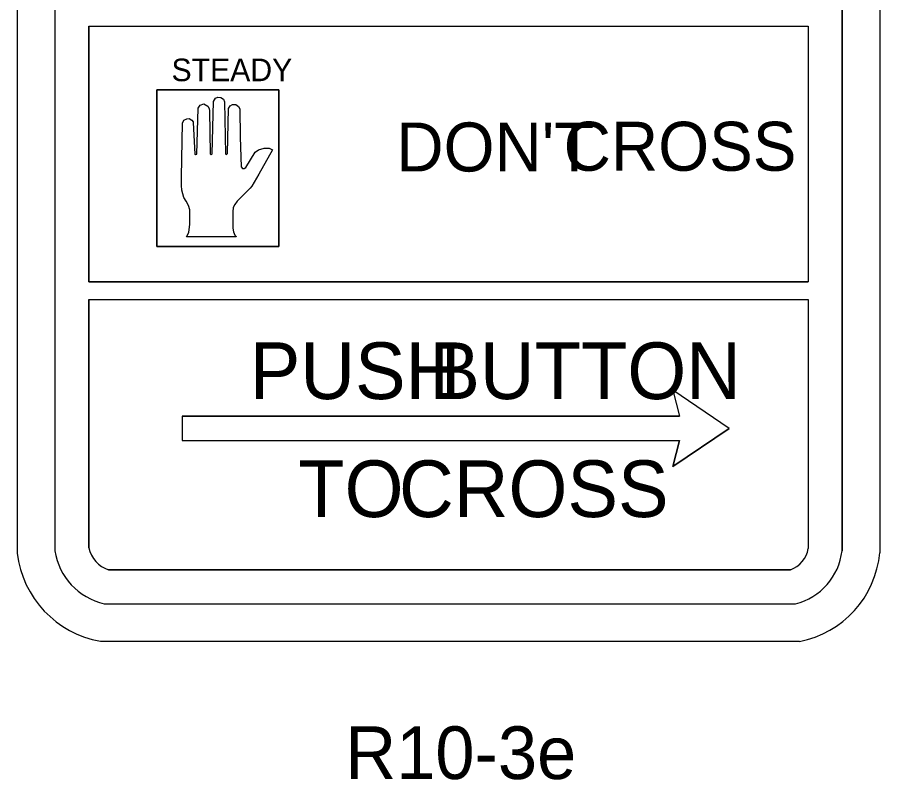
# Model space of a CAD drawing. Extents: x 1896459 to 1901611, y 1616229 to 1617416.
# Drawn here: x 1897736.4 to 1897851.1, y 1616868.6 to 1616970 of the extents above; entities that cross this region are included whole.
import ezdxf

# ---------------------------------------------------------------- set-up
doc = ezdxf.new("R2010")
doc.units = 0
for name, color, linetype in [('Level 8', 7, 'Continuous'), ('ROW_PR_Notes', 7, 'Continuous'), ('Signals_EX_Above Ground', 7, 'Continuous')]:
    doc.layers.add(name, color=color, linetype=linetype)

msp = doc.modelspace()

# ---------------------------------------------------------------- linework, layer by layer
at = {"layer": 'ROW_PR_Notes'}
for p, q in [((1897736.4, 1617066.24), (1897736.4, 1616898.74)), ((1897741.4, 1617066.11), (1897741.4, 1616899.07)), ((1897741.4, 1617066.11), (1897741.4, 1616899.07)), ((1897846.07, 1617066.11), (1897846.07, 1616899.07)), ((1897846.07, 1616899.07), (1897846.07, 1617066.11)), ((1897851.07, 1617066.41), (1897851.07, 1616898.82)), ((1897745.9, 1616968.81), (1897841.57, 1616968.81)), ((1897745.9, 1616968.81), (1897745.9, 1616934.8)), ((1897745.9, 1616934.8), (1897745.9, 1616968.81)), ((1897745.9, 1616968.81), (1897841.57, 1616968.81)), ((1897841.57, 1616968.81), (1897841.57, 1616934.8)), ((1897841.57, 1616968.81), (1897841.57, 1616934.8)), ((1897765.51, 1616940.81), (1897765.52, 1616940.82)), ((1897765.52, 1616940.82), (1897765.51, 1616940.81)), ((1897745.9, 1616934.8), (1897841.57, 1616934.8)), ((1897841.57, 1616934.8), (1897745.9, 1616934.8)), ((1897745.9, 1616932.47), (1897841.57, 1616932.47)), ((1897745.9, 1616932.47), (1897745.9, 1616899.47)), ((1897745.9, 1616899.47), (1897745.9, 1616932.47)), ((1897745.9, 1616932.47), (1897841.57, 1616932.47)), ((1897841.57, 1616932.47), (1897841.57, 1616899.38)), ((1897841.57, 1616932.47), (1897841.57, 1616899.38)), ((1897831.04, 1616915.34), (1897823.56, 1616920.42)), ((1897823.56, 1616920.42), (1897824.44, 1616916.98)), ((1897831.04, 1616915.34), (1897823.56, 1616920.42)), ((1897823.56, 1616920.42), (1897824.44, 1616916.98)), ((1897758.31, 1616916.98), (1897758.31, 1616913.71)), ((1897758.31, 1616916.98), (1897824.44, 1616916.98)), ((1897824.44, 1616916.98), (1897758.31, 1616916.98)), ((1897758.31, 1616916.98), (1897758.31, 1616913.71)), ((1897831.04, 1616915.34), (1897823.56, 1616910.27)), ((1897823.56, 1616910.27), (1897831.04, 1616915.34)), ((1897758.31, 1616913.71), (1897824.44, 1616913.71)), ((1897758.31, 1616913.71), (1897824.44, 1616913.71)), ((1897823.56, 1616910.27), (1897824.44, 1616913.71)), ((1897824.44, 1616913.71), (1897823.56, 1616910.27)), ((1897748.55, 1616896.54), (1897839.22, 1616896.54)), ((1897839.22, 1616896.54), (1897748.55, 1616896.54)), ((1897747.95, 1616892.04), (1897839.86, 1616892.04)), ((1897747.95, 1616892.04), (1897839.86, 1616892.04)), ((1897747.47, 1616887.04), (1897840.39, 1616887.04))]:
    msp.add_line(p, q, dxfattribs=at)
msp.add_lwpolyline([(1897754.95, 1616960.33), (1897771.2, 1616960.33), (1897771.2, 1616939.49), (1897754.95, 1616939.49)], close=True, dxfattribs=at)
for points in [[(1897754.95, 1616939.49), (1897771.2, 1616939.49), (1897771.2, 1616960.33), (1897754.95, 1616960.33), (1897754.95, 1616939.49)], [(1897765.51, 1616940.81), (1897758.89, 1616940.81), (1897759.23, 1616941.38), (1897759.35, 1616942.49), (1897759.36, 1616943.61), (1897759.34, 1616944.37), (1897759.18, 1616944.97), (1897758.86, 1616945.55), (1897758.55, 1616946.04), (1897758.28, 1616947.01), (1897758.22, 1616947.63), (1897758.23, 1616948.75), (1897758.39, 1616955.88), (1897758.55, 1616956.28), (1897758.93, 1616956.48), (1897759.28, 1616956.5), (1897759.62, 1616956.31), (1897759.79, 1616956.1), (1897759.81, 1616955.99), (1897760.02, 1616951.8), (1897760.09, 1616951.7), (1897760.15, 1616951.73), (1897760.27, 1616951.78), (1897760.45, 1616957.9), (1897760.71, 1616958.3), (1897761.22, 1616958.45), (1897761.74, 1616958.18), (1897761.92, 1616957.84), (1897761.94, 1616957.56), (1897762.07, 1616951.84), (1897762.18, 1616951.72), (1897762.32, 1616951.82), (1897762.48, 1616958.79), (1897762.78, 1616959.24), (1897763.08, 1616959.37), (1897763.47, 1616959.33), (1897763.82, 1616959.07), (1897763.96, 1616958.75), (1897764.1, 1616951.82), (1897764.23, 1616951.73), (1897764.35, 1616951.85), (1897764.49, 1616957.86), (1897764.71, 1616958.22), (1897765.01, 1616958.38), (1897765.48, 1616958.4), (1897765.83, 1616958.13), (1897765.98, 1616957.81), (1897766.06, 1616954.05), (1897766.17, 1616950.09), (1897766.34, 1616949.88), (1897766.59, 1616949.86), (1897766.78, 1616950.01), (1897768.04, 1616952.04), (1897768.47, 1616952.36), (1897769.23, 1616952.58), (1897769.89, 1616952.56), (1897770.34, 1616952.36), (1897768.51, 1616949.11), (1897767.61, 1616947.53), (1897767.36, 1616947.25), (1897767.05, 1616946.94), (1897766.57, 1616946.47), (1897766.06, 1616945.92), (1897765.63, 1616945.52), (1897765.31, 1616945.11), (1897765.12, 1616944.68), (1897765.07, 1616944.13), (1897765.08, 1616941.94), (1897765.16, 1616941.45), (1897765.35, 1616941.03), (1897765.52, 1616940.82)]]:
    msp.add_lwpolyline(points, dxfattribs=at)
for centre, radius, start, end in [((1897749.81, 1616900.34), 13.5, 186.8164, 260.0038), ((1897749.81, 1616900.34), 8.5, 188.5933, 257.393), ((1897749.81, 1616900.34), 8.5, 188.5933, 257.393), ((1897749.81, 1616900.34), 4, 192.5385, 251.5824), ((1897749.81, 1616900.34), 4, 192.5385, 251.5824), ((1897837.92, 1616900), 3.69, 290.4443, 350.2331), ((1897837.92, 1616900), 3.69, 290.4443, 350.2331), ((1897837.92, 1616900), 8.19, 283.6872, 353.4463), ((1897837.92, 1616900), 8.19, 283.6872, 353.4463), ((1897837.92, 1616900), 13.2, 280.7764, 354.8365)]:
    msp.add_arc(centre, radius, start, end, dxfattribs=at)
at = {"layer": 'Signals_EX_Above Ground'}
msp.add_lwpolyline([(1897765.51, 1616940.81), (1897758.89, 1616940.81), (1897759.23, 1616941.38), (1897759.35, 1616942.49), (1897759.36, 1616943.61), (1897759.34, 1616944.37), (1897759.18, 1616944.97), (1897758.86, 1616945.55), (1897758.55, 1616946.04), (1897758.28, 1616947.01), (1897758.22, 1616947.63), (1897758.23, 1616948.75), (1897758.39, 1616955.88), (1897758.55, 1616956.28), (1897758.93, 1616956.48), (1897759.28, 1616956.5), (1897759.62, 1616956.31), (1897759.79, 1616956.1), (1897759.81, 1616955.99), (1897760.02, 1616951.8), (1897760.09, 1616951.7), (1897760.15, 1616951.73), (1897760.27, 1616951.78), (1897760.45, 1616957.9), (1897760.71, 1616958.3), (1897761.22, 1616958.45), (1897761.74, 1616958.18), (1897761.92, 1616957.84), (1897761.94, 1616957.56), (1897762.07, 1616951.84), (1897762.18, 1616951.72), (1897762.32, 1616951.82), (1897762.48, 1616958.79), (1897762.78, 1616959.24), (1897763.08, 1616959.37), (1897763.47, 1616959.33), (1897763.82, 1616959.07), (1897763.96, 1616958.75), (1897764.1, 1616951.82), (1897764.23, 1616951.73), (1897764.35, 1616951.85), (1897764.49, 1616957.86), (1897764.71, 1616958.22), (1897765.01, 1616958.38), (1897765.48, 1616958.4), (1897765.83, 1616958.13), (1897765.98, 1616957.81), (1897766.06, 1616954.05), (1897766.17, 1616950.09), (1897766.34, 1616949.88), (1897766.59, 1616949.86), (1897766.78, 1616950.01), (1897768.04, 1616952.04), (1897768.47, 1616952.36), (1897769.23, 1616952.58), (1897769.89, 1616952.56), (1897770.34, 1616952.36), (1897768.51, 1616949.11), (1897767.61, 1616947.53), (1897767.36, 1616947.25), (1897767.05, 1616946.94), (1897766.57, 1616946.47), (1897766.06, 1616945.92), (1897765.63, 1616945.52), (1897765.31, 1616945.11), (1897765.12, 1616944.68), (1897765.07, 1616944.13), (1897765.08, 1616941.94), (1897765.16, 1616941.45), (1897765.35, 1616941.03), (1897765.52, 1616940.82)], dxfattribs=at)

# ---------------------------------------------------------------- texts
at = {"layer": 'Level 8'}
msp.add_text('R10-3e', height=7, dxfattribs=at).set_placement((1897780.02, 1616868.74))
at = {"layer": 'ROW_PR_Notes'}
for s, height, p in [('STEADY', 3.001, (1897756.91, 1616961.48)), ("DON'T", 6.509, (1897786.8, 1616949.48)), ('CROSS', 6.509, (1897809.04, 1616949.58)), ('PUSH', 7.537, (1897767.31, 1616919.23)), ('BUTTON', 7.537, (1897791.19, 1616919.23)), ('TO', 7.537, (1897773.76, 1616903.55)), ('CROSS', 7.537, (1897787.15, 1616903.55))]:
    msp.add_text(s, height=height, dxfattribs=at).set_placement(p)

doc.saveas('drawing.dxf')
